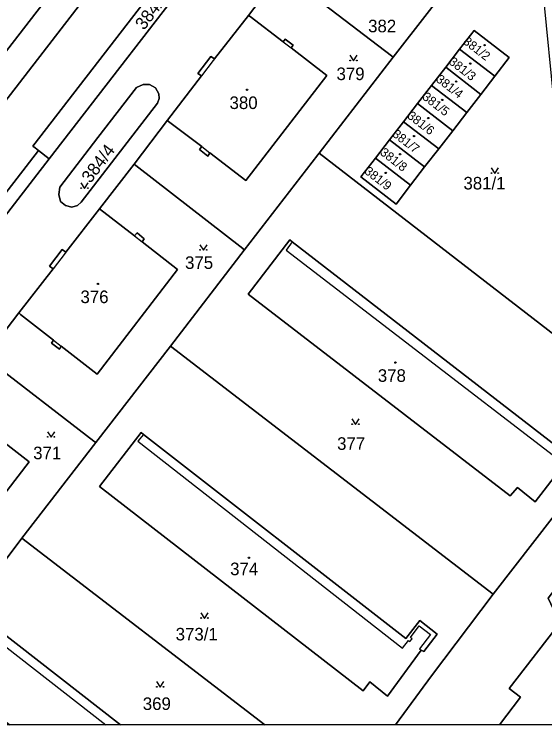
# Model space of a CAD drawing. Extents: x -598934 to -598196, y -1162208 to -1161502.
# Drawn here: x -598875.8 to -598804.1, y -1162207 to -1162110.9 of the extents above; entities that cross this region are included whole.
import ezdxf

# ---------------------------------------------------------------- set-up
doc = ezdxf.new("R2010")
doc.units = 0
for name, color, linetype in [('KN_CAR_KR', 7, 'Continuous'), ('KN_KULTURY', 7, 'Continuous'), ('KN_PARC_CIS_POZ', 7, 'Continuous'), ('KN_PARC_CIS_STAV', 7, 'Continuous'), ('KN_PARC_PLOCHA', 7, 'Continuous'), ('parcely_l', 7, 'Continuous')]:
    doc.layers.add(name, color=color, linetype=linetype)

msp = doc.modelspace()

# ---------------------------------------------------------------- linework, layer by layer
at = {"layer": 'KN_CAR_KR'}
for points in [[(-598839.5, -1162114.67), (-598838.4, -1162115.47)], [(-598848.94, -1162117.17), (-598850.51, -1162119.26)], [(-598848.78, -1162116.96), (-598848.94, -1162117.17)], [(-598850.46, -1162128.82), (-598849.4, -1162129.67)], [(-598859.58, -1162140.89), (-598858.54, -1162141.67)], [(-598838.25, -1162141.69), (-598839.09, -1162142.8)], [(-598868.92, -1162143.2), (-598870.57, -1162145.34)], [(-598868.84, -1162143.1), (-598868.92, -1162143.2)], [(-598839.09, -1162142.8), (-598802.95, -1162170.58)], [(-598870.5, -1162155), (-598869.49, -1162155.79)], [(-598858.37, -1162167.73), (-598859.11, -1162168.64)], [(-598859.11, -1162168.64), (-598823.35, -1162196.62)], [(-598822.37, -1162195.72), (-598822.07, -1162195.36), (-598822.3, -1162195.18), (-598821.09, -1162193.6), (-598819.59, -1162194.75), (-598821.08, -1162196.71)], [(-598879.07, -1162194.8), (-598863.462, -1162206.96)], [(-598823.35, -1162196.62), (-598822.56, -1162195.57)], [(-598822.56, -1162195.57), (-598822.37, -1162195.72)], [(-598821.08, -1162196.71), (-598820.86, -1162196.88)]]:
    msp.add_lwpolyline(points, dxfattribs=at)
at = {"layer": 'KN_KULTURY'}
for points in [[(-598830.482, -1162116.482), (-598829.982, -1162117.232), (-598829.482, -1162116.482)], [(-598811.392, -1162131.692), (-598810.892, -1162132.442), (-598810.392, -1162131.692)], [(-598866.832, -1162133.722), (-598866.332, -1162134.472), (-598865.832, -1162133.722)], [(-598850.762, -1162142.082), (-598850.262, -1162142.832), (-598849.762, -1162142.082)], [(-598830.212, -1162165.622), (-598829.712, -1162166.372), (-598829.212, -1162165.622)], [(-598871.342, -1162167.352), (-598870.842, -1162168.102), (-598870.342, -1162167.352)], [(-598850.612, -1162191.832), (-598850.112, -1162192.582), (-598849.612, -1162191.832)], [(-598856.602, -1162201.132), (-598856.102, -1162201.882), (-598855.602, -1162201.132)]]:
    msp.add_lwpolyline(points, dxfattribs=at)
for centre, radius in [((-598812.28, -1162115.11), 0.09), ((-598812.28, -1162115.11), 0.0398), ((-598830.432, -1162117.181), 0.05), ((-598829.533, -1162117.181), 0.05), ((-598814.21, -1162117.6), 0.09), ((-598814.21, -1162117.6), 0.0398), ((-598816.11, -1162120.04), 0.09), ((-598816.11, -1162120.04), 0.0398), ((-598844.36, -1162121.14), 0.09), ((-598844.36, -1162121.14), 0.0398), ((-598817.99, -1162122.51), 0.09), ((-598817.99, -1162122.51), 0.0398), ((-598819.89, -1162124.96), 0.09), ((-598819.89, -1162124.96), 0.0398), ((-598821.8, -1162127.4), 0.09), ((-598821.8, -1162127.4), 0.0398), ((-598823.69, -1162129.86), 0.09), ((-598823.69, -1162129.86), 0.0398), ((-598825.62, -1162132.37), 0.09), ((-598825.62, -1162132.37), 0.0398), ((-598811.342, -1162132.391), 0.05), ((-598810.443, -1162132.391), 0.05), ((-598866.782, -1162134.421), 0.05), ((-598865.883, -1162134.421), 0.05), ((-598850.712, -1162142.781), 0.05), ((-598849.813, -1162142.781), 0.05), ((-598864.5, -1162147.37), 0.09), ((-598864.5, -1162147.37), 0.0398), ((-598824.32, -1162158.01), 0.09), ((-598824.32, -1162158.01), 0.0398), ((-598830.162, -1162166.321), 0.05), ((-598829.263, -1162166.321), 0.05), ((-598871.292, -1162168.051), 0.05), ((-598870.393, -1162168.051), 0.05), ((-598844.11, -1162184.39), 0.09), ((-598844.11, -1162184.39), 0.0398), ((-598850.562, -1162192.531), 0.05), ((-598849.663, -1162192.531), 0.05), ((-598856.552, -1162201.831), 0.05), ((-598855.653, -1162201.831), 0.05)]:
    msp.add_circle(centre, radius, dxfattribs=at)
at = {"layer": 'KN_PARC_PLOCHA'}
for points in [[(-598840.79, -1162062.93), (-598837.76, -1162065.26), (-598881.48, -1162121.83), (-598880.27, -1162122.81), (-598901.94, -1162150.79), (-598901.53, -1162151.13), (-598902.16, -1162151.9), (-598902.58, -1162151.62), (-598917.58, -1162171.02), (-598932.017, -1162189.781), (-598932.017, -1162174.389), (-598931.87, -1162174.2), (-598924.54, -1162164.69), (-598917.29, -1162155.14), (-598912.37, -1162148.88), (-598906.19, -1162140.84), (-598887.39, -1162116.58), (-598881.32, -1162108.67), (-598869.09, -1162092.74), (-598862.5, -1162084.05), (-598855.63, -1162075.16), (-598844.17, -1162060.34)], [(-598834.62, -1162067.66), (-598878.34, -1162124.34), (-598878.7, -1162124.05), (-598879.19, -1162123.66), (-598880.27, -1162122.81), (-598881.48, -1162121.83), (-598837.76, -1162065.26)], [(-598829.3, -1162071.75), (-598873.32, -1162128.74), (-598873, -1162128.98), (-598872.52, -1162129.34), (-598908.85, -1162176.37), (-598932.017, -1162206.357), (-598932.017, -1162192.125), (-598915.91, -1162171.29), (-598879.19, -1162123.66), (-598878.7, -1162124.05), (-598878.34, -1162124.34), (-598834.62, -1162067.66)], [(-598827.04, -1162073.49), (-598871.08, -1162130.49), (-598872.52, -1162129.34), (-598873, -1162128.98), (-598873.32, -1162128.74), (-598829.3, -1162071.75)], [(-598811.61, -1162092.7), (-598810.22, -1162098.19), (-598824.62, -1162116.72), (-598824.86, -1162116.55), (-598839.44, -1162105.38), (-598839.7, -1162105.21), (-598835.07, -1162099.17), (-598834.89, -1162099.35), (-598830.42, -1162102.78), (-598830.76, -1162103.28), (-598829.66, -1162104.09), (-598829.35, -1162103.56), (-598824.4, -1162107.36), (-598813.45, -1162093.17), (-598823.89, -1162085.14), (-598824.11, -1162084.95), (-598819.62, -1162079.18), (-598816.36, -1162081.67)], [(-598799.76, -1162156.64), (-598834.61, -1162129.69), (-598824.62, -1162116.72), (-598810.22, -1162098.19), (-598811.61, -1162092.7), (-598804.67, -1162105.09), (-598802.58, -1162126.61), (-598800.7, -1162145.7)], [(-598824.62, -1162116.72), (-598834.61, -1162129.69), (-598834.82, -1162129.94), (-598844.75, -1162142.82), (-598844.93, -1162142.58), (-598859.41, -1162131.37), (-598859.61, -1162131.19), (-598855.1, -1162125.25), (-598854.99, -1162125.43), (-598850.46, -1162128.82), (-598850.77, -1162129.23), (-598849.66, -1162130.1), (-598849.4, -1162129.67), (-598844.54, -1162133.41), (-598833.57, -1162119.19), (-598838.4, -1162115.47), (-598838.15, -1162115.1), (-598839.21, -1162114.28), (-598839.5, -1162114.67), (-598843.93, -1162111.25), (-598844.18, -1162111.08), (-598839.7, -1162105.21), (-598839.44, -1162105.38), (-598824.86, -1162116.55)], [(-598855.1, -1162125.25), (-598850.51, -1162119.26), (-598851, -1162118.94), (-598849.27, -1162116.64), (-598848.78, -1162116.96), (-598844.18, -1162111.08), (-598843.93, -1162111.25), (-598839.5, -1162114.67), (-598839.21, -1162114.28), (-598838.15, -1162115.1), (-598838.4, -1162115.47), (-598833.57, -1162119.19), (-598844.54, -1162133.41), (-598849.4, -1162129.67), (-598849.66, -1162130.1), (-598850.77, -1162129.23), (-598850.46, -1162128.82), (-598854.99, -1162125.43)], [(-598822.26, -1162134.02), (-598820.37, -1162131.57), (-598818.47, -1162129.12), (-598816.57, -1162126.67), (-598814.68, -1162124.21), (-598812.78, -1162121.76), (-598810.89, -1162119.31), (-598808.93, -1162116.78), (-598813.68, -1162113.11), (-598815.64, -1162115.64), (-598817.53, -1162118.09), (-598819.43, -1162120.55), (-598821.32, -1162123), (-598823.22, -1162125.45), (-598825.12, -1162127.91), (-598827.01, -1162130.36), (-598828.99, -1162132.92), (-598824.24, -1162136.59)], [(-598810.89, -1162119.31), (-598815.64, -1162115.64), (-598813.68, -1162113.11), (-598808.93, -1162116.78)], [(-598810.89, -1162119.31), (-598812.78, -1162121.76), (-598817.53, -1162118.09), (-598815.64, -1162115.64)], [(-598812.78, -1162121.76), (-598814.68, -1162124.21), (-598819.43, -1162120.55), (-598817.53, -1162118.09)], [(-598867.28, -1162136.77), (-598868.03, -1162136.99), (-598868.9, -1162136.8), (-598869.55, -1162136.22), (-598869.78, -1162135.29), (-598869.65, -1162134.29), (-598864.51, -1162127.59), (-598859.3, -1162120.84), (-598858.41, -1162120.43), (-598857.54, -1162120.41), (-598856.73, -1162120.87), (-598856.29, -1162121.67), (-598856.25, -1162122.33), (-598856.44, -1162122.96), (-598866.79, -1162136.35)], [(-598867.28, -1162136.77), (-598866.79, -1162136.35), (-598856.44, -1162122.96), (-598856.25, -1162122.33), (-598856.29, -1162121.67), (-598856.73, -1162120.87), (-598857.54, -1162120.41), (-598858.41, -1162120.43), (-598859.3, -1162120.84), (-598864.51, -1162127.59), (-598869.65, -1162134.29), (-598869.78, -1162135.29), (-598869.55, -1162136.22), (-598868.9, -1162136.8), (-598868.03, -1162136.99)], [(-598814.68, -1162124.21), (-598816.57, -1162126.67), (-598821.32, -1162123), (-598819.43, -1162120.55)], [(-598816.57, -1162126.67), (-598818.47, -1162129.12), (-598823.22, -1162125.45), (-598821.32, -1162123)], [(-598818.47, -1162129.12), (-598820.37, -1162131.57), (-598825.12, -1162127.91), (-598823.22, -1162125.45)], [(-598820.37, -1162131.57), (-598822.26, -1162134.02), (-598827.01, -1162130.36), (-598825.12, -1162127.91)], [(-598871.08, -1162130.49), (-598907.4, -1162177.57), (-598930.113, -1162206.96), (-598932.017, -1162206.96), (-598932.017, -1162206.357), (-598908.85, -1162176.37), (-598872.52, -1162129.34)], [(-598799.76, -1162156.64), (-598798.41, -1162164.9), (-598797.5, -1162171.77), (-598811.1, -1162189.32), (-598854.7, -1162155.77), (-598844.75, -1162142.82), (-598834.82, -1162129.94), (-598834.61, -1162129.69)], [(-598822.26, -1162134.02), (-598824.24, -1162136.59), (-598828.99, -1162132.92), (-598827.01, -1162130.36)], [(-598844.75, -1162142.82), (-598854.7, -1162155.77), (-598864.79, -1162168.83), (-598865.06, -1162168.64), (-598879.58, -1162157.47), (-598879.77, -1162157.27), (-598875.19, -1162151.29), (-598874.96, -1162151.53), (-598870.5, -1162155), (-598870.78, -1162155.4), (-598869.72, -1162156.21), (-598869.49, -1162155.79), (-598864.62, -1162159.59), (-598853.76, -1162145.41), (-598858.54, -1162141.67), (-598858.25, -1162141.28), (-598859.22, -1162140.48), (-598859.58, -1162140.89), (-598864.28, -1162137.23), (-598859.61, -1162131.19), (-598859.41, -1162131.37), (-598844.93, -1162142.58)], [(-598875.19, -1162151.29), (-598870.57, -1162145.34), (-598871.04, -1162144.99), (-598869.32, -1162142.74), (-598868.84, -1162143.1), (-598864.28, -1162137.23), (-598859.58, -1162140.89), (-598859.22, -1162140.48), (-598858.25, -1162141.28), (-598858.54, -1162141.67), (-598853.76, -1162145.41), (-598864.62, -1162159.59), (-598869.49, -1162155.79), (-598869.72, -1162156.21), (-598870.78, -1162155.4), (-598870.5, -1162155), (-598874.96, -1162151.53)], [(-598838.25, -1162141.69), (-598802.58, -1162169.31), (-598801.19, -1162167.5), (-598799.44, -1162168.84), (-598800.86, -1162170.68), (-598800.59, -1162170.9), (-598800.87, -1162170.93), (-598805.45, -1162176.82), (-598807.84, -1162174.87), (-598808.82, -1162176.03), (-598844.21, -1162148.75), (-598838.58, -1162141.4)], [(-598838.25, -1162141.69), (-598838.58, -1162141.4), (-598844.21, -1162148.75), (-598808.82, -1162176.03), (-598807.84, -1162174.87), (-598805.45, -1162176.82), (-598800.87, -1162170.93), (-598800.59, -1162170.9), (-598800.86, -1162170.68), (-598799.44, -1162168.84), (-598801.19, -1162167.5), (-598802.58, -1162169.31)], [(-598811.1, -1162189.32), (-598819.43, -1162200.35), (-598824.314, -1162206.96), (-598841.961, -1162206.96), (-598874.8, -1162181.74), (-598864.79, -1162168.83), (-598854.7, -1162155.77)], [(-598864.79, -1162168.83), (-598874.8, -1162181.74), (-598884.74, -1162194.99), (-598885.02, -1162194.67), (-598899.65, -1162183.36), (-598899.81, -1162183.21), (-598895.29, -1162177.34), (-598895.07, -1162177.47), (-598890.47, -1162181.02), (-598890.8, -1162181.41), (-598889.8, -1162182.22), (-598889.51, -1162181.8), (-598884.71, -1162185.57), (-598873.82, -1162171.44), (-598878.69, -1162167.63), (-598878.4, -1162167.21), (-598879.36, -1162166.39), (-598879.72, -1162166.87), (-598884.19, -1162163.44), (-598884.38, -1162163.24), (-598879.77, -1162157.27), (-598879.58, -1162157.47), (-598865.06, -1162168.64)], [(-598895.29, -1162177.34), (-598890.63, -1162171.34), (-598888.94, -1162169.17), (-598884.38, -1162163.24), (-598884.19, -1162163.44), (-598879.72, -1162166.87), (-598879.36, -1162166.39), (-598878.4, -1162167.21), (-598878.69, -1162167.63), (-598873.82, -1162171.44), (-598884.71, -1162185.57), (-598889.51, -1162181.8), (-598889.8, -1162182.22), (-598890.8, -1162181.41), (-598890.47, -1162181.02), (-598895.07, -1162177.47)], [(-598858.37, -1162167.73), (-598858.66, -1162167.44), (-598864.3, -1162174.76), (-598828.66, -1162202.36), (-598827.76, -1162201.16), (-598825.37, -1162203.11), (-598820.86, -1162196.88), (-598820.5, -1162197.07), (-598818.66, -1162194.7), (-598821.04, -1162192.86), (-598822.92, -1162195.29)], [(-598858.37, -1162167.73), (-598822.92, -1162195.29), (-598821.04, -1162192.86), (-598818.66, -1162194.7), (-598820.5, -1162197.07), (-598820.86, -1162196.88), (-598825.37, -1162203.11), (-598827.76, -1162201.16), (-598828.66, -1162202.36), (-598864.3, -1162174.76), (-598858.66, -1162167.44)], [(-598794.55, -1162186.38), (-598795.14, -1162185.93), (-598796.57, -1162185.37), (-598798.06, -1162185.34), (-598799.49, -1162185.74), (-598800.77, -1162186.51), (-598801.87, -1162187.51), (-598803.67, -1162189.86), (-598802.64, -1162192.04), (-598801.71, -1162192.7), (-598808.95, -1162202.06), (-598807.4, -1162203.24), (-598810.269, -1162206.96), (-598824.314, -1162206.96), (-598819.43, -1162200.35), (-598811.1, -1162189.32), (-598797.5, -1162171.77), (-598795.03, -1162183.32)], [(-598841.961, -1162206.96), (-598861.437, -1162206.96), (-598878.27, -1162193.88), (-598878.62, -1162193.55), (-598884.28, -1162200.86), (-598876.444, -1162206.96), (-598893.998, -1162206.96), (-598884.74, -1162194.99), (-598874.8, -1162181.74)], [(-598794.55, -1162186.38), (-598793.75, -1162187.77), (-598790.708, -1162206.96), (-598810.269, -1162206.96), (-598807.4, -1162203.24), (-598808.95, -1162202.06), (-598801.71, -1162192.7), (-598802.64, -1162192.04), (-598803.67, -1162189.86), (-598801.87, -1162187.51), (-598800.77, -1162186.51), (-598799.49, -1162185.74), (-598798.06, -1162185.34), (-598796.57, -1162185.37), (-598795.14, -1162185.93)], [(-598861.437, -1162206.96), (-598876.444, -1162206.96), (-598884.28, -1162200.86), (-598878.62, -1162193.55), (-598878.27, -1162193.88)]]:
    msp.add_lwpolyline(points, close=True, dxfattribs=at)
for points in [[(-598907.4, -1162177.57), (-598871.08, -1162130.49), (-598827.04, -1162073.49)], [(-598839.7, -1162105.21), (-598844.18, -1162111.08), (-598848.78, -1162116.96), (-598849.27, -1162116.64), (-598851, -1162118.94), (-598850.51, -1162119.26), (-598855.1, -1162125.25), (-598859.61, -1162131.19), (-598864.28, -1162137.23), (-598868.84, -1162143.1), (-598869.32, -1162142.74), (-598871.04, -1162144.99), (-598870.57, -1162145.34), (-598875.19, -1162151.29), (-598879.77, -1162157.27)]]:
    msp.add_lwpolyline(points, dxfattribs=at)
at = {"layer": 'parcely_l'}
for points in [[(-598837.76, -1162065.26), (-598881.48, -1162121.83), (-598880.27, -1162122.81)], [(-598879.19, -1162123.66), (-598878.7, -1162124.05), (-598878.34, -1162124.34), (-598834.62, -1162067.66)], [(-598829.3, -1162071.75), (-598873.32, -1162128.74), (-598873, -1162128.98), (-598872.52, -1162129.34)], [(-598827.04, -1162073.49), (-598871.08, -1162130.49)], [(-598811.61, -1162092.7), (-598810.22, -1162098.19), (-598824.62, -1162116.72)], [(-598844.18, -1162111.08), (-598839.7, -1162105.21)], [(-598824.62, -1162116.72), (-598824.86, -1162116.55), (-598839.44, -1162105.38), (-598839.7, -1162105.21)], [(-598855.1, -1162125.25), (-598854.99, -1162125.43), (-598850.46, -1162128.82), (-598850.77, -1162129.23), (-598849.66, -1162130.1), (-598849.4, -1162129.67), (-598844.54, -1162133.41), (-598833.57, -1162119.19), (-598838.4, -1162115.47), (-598838.15, -1162115.1), (-598839.21, -1162114.28), (-598839.5, -1162114.67), (-598843.93, -1162111.25), (-598844.18, -1162111.08)], [(-598844.18, -1162111.08), (-598848.78, -1162116.96), (-598849.27, -1162116.64), (-598851, -1162118.94), (-598850.51, -1162119.26), (-598855.1, -1162125.25)], [(-598810.89, -1162119.31), (-598808.93, -1162116.78), (-598813.68, -1162113.11), (-598815.64, -1162115.64)], [(-598817.53, -1162118.09), (-598815.64, -1162115.64)], [(-598815.64, -1162115.64), (-598810.89, -1162119.31)], [(-598824.62, -1162116.72), (-598834.61, -1162129.69)], [(-598819.43, -1162120.55), (-598817.53, -1162118.09)], [(-598817.53, -1162118.09), (-598812.78, -1162121.76)], [(-598810.89, -1162119.31), (-598812.78, -1162121.76)], [(-598867.28, -1162136.77), (-598866.79, -1162136.35), (-598856.44, -1162122.96), (-598856.25, -1162122.33), (-598856.29, -1162121.67), (-598856.73, -1162120.87), (-598857.54, -1162120.41), (-598858.41, -1162120.43), (-598859.3, -1162120.84), (-598864.51, -1162127.59), (-598869.65, -1162134.29), (-598869.78, -1162135.29), (-598869.55, -1162136.22), (-598868.9, -1162136.8), (-598868.03, -1162136.99), (-598867.28, -1162136.77)], [(-598821.32, -1162123), (-598819.43, -1162120.55)], [(-598814.68, -1162124.21), (-598819.43, -1162120.55)], [(-598812.78, -1162121.76), (-598814.68, -1162124.21)], [(-598821.32, -1162123), (-598823.22, -1162125.45)], [(-598816.57, -1162126.67), (-598821.32, -1162123)], [(-598814.68, -1162124.21), (-598816.57, -1162126.67)], [(-598859.61, -1162131.19), (-598855.1, -1162125.25)], [(-598825.12, -1162127.91), (-598823.22, -1162125.45)], [(-598823.22, -1162125.45), (-598818.47, -1162129.12)], [(-598818.47, -1162129.12), (-598816.57, -1162126.67)], [(-598827.01, -1162130.36), (-598825.12, -1162127.91)], [(-598825.12, -1162127.91), (-598820.37, -1162131.57)], [(-598872.52, -1162129.34), (-598908.85, -1162176.37), (-598932.017, -1162206.357)], [(-598871.08, -1162130.49), (-598872.52, -1162129.34)], [(-598834.61, -1162129.69), (-598834.82, -1162129.94), (-598844.75, -1162142.82)], [(-598834.61, -1162129.69), (-598799.76, -1162156.64)], [(-598818.47, -1162129.12), (-598820.37, -1162131.57)], [(-598871.08, -1162130.49), (-598907.4, -1162177.57), (-598930.113, -1162206.96)], [(-598822.26, -1162134.02), (-598824.24, -1162136.59), (-598828.99, -1162132.92), (-598827.01, -1162130.36)], [(-598827.01, -1162130.36), (-598822.26, -1162134.02)], [(-598859.61, -1162131.19), (-598864.28, -1162137.23)], [(-598844.75, -1162142.82), (-598844.93, -1162142.58), (-598859.41, -1162131.37), (-598859.61, -1162131.19)], [(-598820.37, -1162131.57), (-598822.26, -1162134.02)], [(-598875.19, -1162151.29), (-598870.57, -1162145.34), (-598871.04, -1162144.99), (-598869.32, -1162142.74), (-598868.84, -1162143.1), (-598864.28, -1162137.23)], [(-598864.28, -1162137.23), (-598859.58, -1162140.89), (-598859.22, -1162140.48), (-598858.25, -1162141.28), (-598858.54, -1162141.67), (-598853.76, -1162145.41), (-598864.62, -1162159.59), (-598869.49, -1162155.79), (-598869.72, -1162156.21), (-598870.78, -1162155.4), (-598870.5, -1162155), (-598874.96, -1162151.53), (-598875.19, -1162151.29)], [(-598838.25, -1162141.69), (-598838.58, -1162141.4), (-598844.21, -1162148.75), (-598808.82, -1162176.03), (-598807.84, -1162174.87), (-598805.45, -1162176.82), (-598800.87, -1162170.93), (-598800.59, -1162170.9), (-598800.86, -1162170.68), (-598799.44, -1162168.84), (-598801.19, -1162167.5), (-598802.58, -1162169.31), (-598838.25, -1162141.69)], [(-598854.7, -1162155.77), (-598844.75, -1162142.82)], [(-598875.19, -1162151.29), (-598879.77, -1162157.27)], [(-598864.79, -1162168.83), (-598854.7, -1162155.77)], [(-598854.7, -1162155.77), (-598811.1, -1162189.32)], [(-598879.77, -1162157.27), (-598879.58, -1162157.47), (-598865.06, -1162168.64), (-598864.79, -1162168.83)], [(-598895.29, -1162177.34), (-598895.07, -1162177.47), (-598890.47, -1162181.02), (-598890.8, -1162181.41), (-598889.8, -1162182.22), (-598889.51, -1162181.8), (-598884.71, -1162185.57), (-598873.82, -1162171.44), (-598878.69, -1162167.63), (-598878.4, -1162167.21), (-598879.36, -1162166.39), (-598879.72, -1162166.87), (-598884.19, -1162163.44), (-598884.38, -1162163.24)], [(-598858.37, -1162167.73), (-598822.92, -1162195.29), (-598821.04, -1162192.86), (-598818.66, -1162194.7), (-598820.5, -1162197.07), (-598820.86, -1162196.88), (-598825.37, -1162203.11), (-598827.76, -1162201.16), (-598828.66, -1162202.36), (-598864.3, -1162174.76), (-598858.66, -1162167.44), (-598858.37, -1162167.73)], [(-598864.79, -1162168.83), (-598874.8, -1162181.74)], [(-598811.1, -1162189.32), (-598797.5, -1162171.77)], [(-598874.8, -1162181.74), (-598884.74, -1162194.99)], [(-598841.961, -1162206.96), (-598874.8, -1162181.74)], [(-598794.55, -1162186.38), (-598795.14, -1162185.93), (-598796.57, -1162185.37), (-598798.06, -1162185.34), (-598799.49, -1162185.74), (-598800.77, -1162186.51), (-598801.87, -1162187.51), (-598803.67, -1162189.86), (-598802.64, -1162192.04), (-598801.71, -1162192.7), (-598808.95, -1162202.06), (-598807.4, -1162203.24), (-598810.269, -1162206.96)], [(-598811.1, -1162189.32), (-598819.43, -1162200.35), (-598824.314, -1162206.96)], [(-598876.444, -1162206.96), (-598884.28, -1162200.86), (-598878.62, -1162193.55), (-598878.27, -1162193.88), (-598861.437, -1162206.96)], [(-598861.437, -1162206.96), (-598876.444, -1162206.96)], [(-598841.961, -1162206.96), (-598861.437, -1162206.96)], [(-598824.314, -1162206.96), (-598841.961, -1162206.96)], [(-598810.269, -1162206.96), (-598824.314, -1162206.96)], [(-598790.708, -1162206.96), (-598810.269, -1162206.96)]]:
    msp.add_lwpolyline(points, dxfattribs=at)

# ---------------------------------------------------------------- texts
at = {"layer": 'KN_PARC_CIS_POZ'}
for s, rotation, p in [('384/21', 53.10044, (-598858.271, -1162113.173)), ('384/4', 53.10017, (-598865.516, -1162133.873))]:
    msp.add_text(s, height=1.7, rotation=rotation, dxfattribs=at).set_placement(p)
for s, p in [('382', (-598828.007, -1162113.37)), ('379', (-598832.277, -1162119.83)), ('381/1', (-598815.127, -1162134.61)), ('375', (-598852.737, -1162145.35)), ('377', (-598832.197, -1162169.8)), ('371', (-598873.257, -1162171.07)), ('373/1', (-598854.007, -1162195.56)), ('369', (-598858.447, -1162204.96))]:
    msp.add_text(s, height=1.7, dxfattribs=at).set_placement(p)
at = {"layer": 'KN_PARC_CIS_STAV'}
for s, p in [('381/2', (-598815.272, -1162114.814)), ('381/3', (-598817.202, -1162117.544)), ('381/4', (-598818.942, -1162119.924)), ('381/5', (-598820.782, -1162122.304)), ('381/6', (-598822.812, -1162124.864)), ('381/7', (-598824.832, -1162127.334)), ('381/8', (-598826.492, -1162129.804)), ('381/9', (-598828.602, -1162132.354))]:
    msp.add_text(s, height=1.2, rotation=322.20123, dxfattribs=at).set_placement(p)
for s, p in [('380', (-598846.727, -1162123.74)), ('376', (-598866.867, -1162149.97)), ('378', (-598826.697, -1162160.61)), ('374', (-598846.647, -1162186.74))]:
    msp.add_text(s, height=1.7, dxfattribs=at).set_placement(p)

doc.saveas('drawing.dxf')
